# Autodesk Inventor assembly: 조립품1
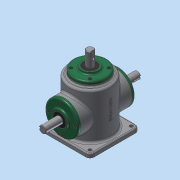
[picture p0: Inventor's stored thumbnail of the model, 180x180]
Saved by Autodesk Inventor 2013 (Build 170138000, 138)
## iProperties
Created: 2015-10
Part Number: 조립품1
Document SubType Name: Assembly
Designer: dgall
Author: dgall
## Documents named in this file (14)
- C:\Users\dgall\Desktop\451007V1016\조립품1.iam
- C:\Users\dgall\Desktop\451007V1016\1본체.ipt
- C:\Users\dgall\Desktop\451007V1016\커버.ipt
- C:\Users\dgall\Desktop\451007V1016\오일실.ipt
- C:\Users\dgall\Desktop\451007V1016\베어링 6203.ipt
- C:\Users\dgall\Desktop\451007V1016\메인 축.ipt
- 메인 축.ipt
- C:\Users\dgall\Desktop\451007V1016\서브 축.ipt
- 서브 축.ipt
- C:\Users\dgall\Desktop\451007V1016\키 5x5.ipt
- C:\Users\dgall\Desktop\451007V1016\키 4x4.ipt
- C:\Users\dgall\Desktop\451007V1016\메인 베벨기어.ipt
- C:\Users\dgall\Desktop\451007V1016\서브 베벨기어.ipt
- C:\Users\dgall\Desktop\451007V1016\M4.ipt
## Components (13 placed, 2 different names)
1. 1본체:1
2. M4:1
3. M4:2
4. M4:3
5. M4:4
6. M4:5
7. M4:6
8. M4:7
9. M4:8
10. M4:9
11. M4:10
12. M4:11
13. M4:12
